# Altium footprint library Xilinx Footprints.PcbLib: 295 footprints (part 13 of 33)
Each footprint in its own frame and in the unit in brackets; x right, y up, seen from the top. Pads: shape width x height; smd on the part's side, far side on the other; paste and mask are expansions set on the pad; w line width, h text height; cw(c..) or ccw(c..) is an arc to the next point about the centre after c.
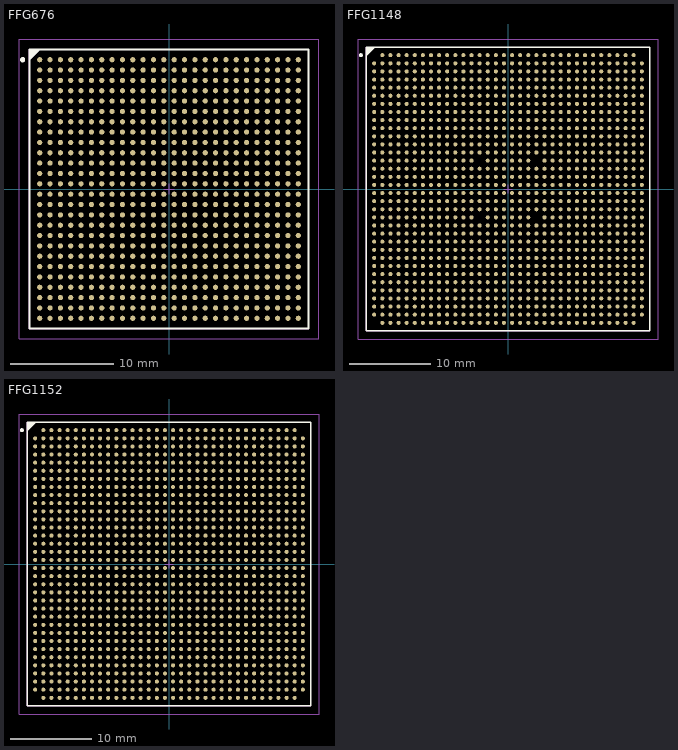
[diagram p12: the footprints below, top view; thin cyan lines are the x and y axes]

## FFG676 [mm] "676-Ball Flip Chip Fine Pitch Ball Grid Array (FFG676) - Pb-Free"
height 3
pads (676):
  round 0.5 smd: A1(-12.5,12.5) A2(-11.5,12.5) A3(-10.5,12.5) A4(-9.5,12.5) A5(-8.5,12.5) A6(-7.5,12.5) A7(-6.5,12.5) A8(-5.5,12.5) A9(-4.5,12.5) A10(-3.5,12.5) A11(-2.5,12.5) A12(-1.5,12.5) A13(-0.5,12.5) A14(0.5,12.5) A15(1.5,12.5) A16(2.5,12.5) A17(3.5,12.5) A18(4.5,12.5) A19(5.5,12.5) A20(6.5,12.5) A21(7.5,12.5) A22(8.5,12.5) A23(9.5,12.5) A24(10.5,12.5) A25(11.5,12.5) A26(12.5,12.5) AA1(-12.5,-7.5) AA2(-11.5,-7.5) AA3(-10.5,-7.5) AA4(-9.5,-7.5) AA5(-8.5,-7.5) AA6(-7.5,-7.5) AA7(-6.5,-7.5) AA8(-5.5,-7.5) AA9(-4.5,-7.5) AA10(-3.5,-7.5) AA11(-2.5,-7.5) AA12(-1.5,-7.5) AA13(-0.5,-7.5) AA14(0.5,-7.5) AA15(1.5,-7.5) AA16(2.5,-7.5) AA17(3.5,-7.5) AA18(4.5,-7.5) AA19(5.5,-7.5) AA20(6.5,-7.5) AA21(7.5,-7.5) AA22(8.5,-7.5) AA23(9.5,-7.5) AA24(10.5,-7.5) AA25(11.5,-7.5) AA26(12.5,-7.5) AB1(-12.5,-8.5) AB2(-11.5,-8.5) AB3(-10.5,-8.5) AB4(-9.5,-8.5) AB5(-8.5,-8.5) AB6(-7.5,-8.5) AB7(-6.5,-8.5) AB8(-5.5,-8.5) AB9(-4.5,-8.5) AB10(-3.5,-8.5) AB11(-2.5,-8.5) AB12(-1.5,-8.5) AB13(-0.5,-8.5) AB14(0.5,-8.5) AB15(1.5,-8.5) AB16(2.5,-8.5) AB17(3.5,-8.5) AB18(4.5,-8.5) AB19(5.5,-8.5) AB20(6.5,-8.5) AB21(7.5,-8.5) AB22(8.5,-8.5) AB23(9.5,-8.5) AB24(10.5,-8.5) AB25(11.5,-8.5) AB26(12.5,-8.5) AC1(-12.5,-9.5) AC2(-11.5,-9.5) AC3(-10.5,-9.5) AC4(-9.5,-9.5) AC5(-8.5,-9.5) AC6(-7.5,-9.5) AC7(-6.5,-9.5) AC8(-5.5,-9.5) AC9(-4.5,-9.5) AC10(-3.5,-9.5) AC11(-2.5,-9.5) AC12(-1.5,-9.5) AC13(-0.5,-9.5) AC14(0.5,-9.5) AC15(1.5,-9.5) AC16(2.5,-9.5) AC17(3.5,-9.5) AC18(4.5,-9.5) AC19(5.5,-9.5) AC20(6.5,-9.5) AC21(7.5,-9.5) AC22(8.5,-9.5) AC23(9.5,-9.5) AC24(10.5,-9.5) AC25(11.5,-9.5) AC26(12.5,-9.5) AD1(-12.5,-10.5) AD2(-11.5,-10.5) AD3(-10.5,-10.5) AD4(-9.5,-10.5) AD5(-8.5,-10.5) AD6(-7.5,-10.5) AD7(-6.5,-10.5) AD8(-5.5,-10.5) AD9(-4.5,-10.5) AD10(-3.5,-10.5) AD11(-2.5,-10.5) AD12(-1.5,-10.5) AD13(-0.5,-10.5) AD14(0.5,-10.5) AD15(1.5,-10.5) AD16(2.5,-10.5) AD17(3.5,-10.5) AD18(4.5,-10.5) AD19(5.5,-10.5) AD20(6.5,-10.5) AD21(7.5,-10.5) AD22(8.5,-10.5) AD23(9.5,-10.5) AD24(10.5,-10.5) AD25(11.5,-10.5) AD26(12.5,-10.5) AE1(-12.5,-11.5) AE2(-11.5,-11.5) AE3(-10.5,-11.5) AE4(-9.5,-11.5) AE5(-8.5,-11.5) AE6(-7.5,-11.5) AE7(-6.5,-11.5) AE8(-5.5,-11.5) AE9(-4.5,-11.5) AE10(-3.5,-11.5) AE11(-2.5,-11.5) AE12(-1.5,-11.5) AE13(-0.5,-11.5) AE14(0.5,-11.5) AE15(1.5,-11.5) AE16(2.5,-11.5) AE17(3.5,-11.5) AE18(4.5,-11.5) AE19(5.5,-11.5) AE20(6.5,-11.5) AE21(7.5,-11.5) AE22(8.5,-11.5) AE23(9.5,-11.5) AE24(10.5,-11.5) AE25(11.5,-11.5) AE26(12.5,-11.5) AF1(-12.5,-12.5) AF2(-11.5,-12.5) AF3(-10.5,-12.5) AF4(-9.5,-12.5) AF5(-8.5,-12.5) AF6(-7.5,-12.5) AF7(-6.5,-12.5) AF8(-5.5,-12.5) AF9(-4.5,-12.5) AF10(-3.5,-12.5) AF11(-2.5,-12.5) AF12(-1.5,-12.5) AF13(-0.5,-12.5) AF14(0.5,-12.5) AF15(1.5,-12.5) AF16(2.5,-12.5) AF17(3.5,-12.5) AF18(4.5,-12.5) AF19(5.5,-12.5) AF20(6.5,-12.5) AF21(7.5,-12.5) AF22(8.5,-12.5) AF23(9.5,-12.5) AF24(10.5,-12.5) AF25(11.5,-12.5) AF26(12.5,-12.5) B1(-12.5,11.5) B2(-11.5,11.5) B3(-10.5,11.5) B4(-9.5,11.5) B5(-8.5,11.5) B6(-7.5,11.5) B7(-6.5,11.5) B8(-5.5,11.5) B9(-4.5,11.5) B10(-3.5,11.5) B11(-2.5,11.5) B12(-1.5,11.5) B13(-0.5,11.5) B14(0.5,11.5) B15(1.5,11.5) B16(2.5,11.5) B17(3.5,11.5) B18(4.5,11.5) B19(5.5,11.5) B20(6.5,11.5) B21(7.5,11.5) B22(8.5,11.5) B23(9.5,11.5) B24(10.5,11.5) B25(11.5,11.5) B26(12.5,11.5) C1(-12.5,10.5) C2(-11.5,10.5) C3(-10.5,10.5) C4(-9.5,10.5) C5(-8.5,10.5) C6(-7.5,10.5) C7(-6.5,10.5) C8(-5.5,10.5) C9(-4.5,10.5) C10(-3.5,10.5) C11(-2.5,10.5) C12(-1.5,10.5) C13(-0.5,10.5) C14(0.5,10.5) C15(1.5,10.5) C16(2.5,10.5) C17(3.5,10.5) C18(4.5,10.5) C19(5.5,10.5) C20(6.5,10.5) C21(7.5,10.5) C22(8.5,10.5) C23(9.5,10.5) C24(10.5,10.5) C25(11.5,10.5) C26(12.5,10.5) D1(-12.5,9.5) D2(-11.5,9.5) D3(-10.5,9.5) D4(-9.5,9.5) D5(-8.5,9.5) D6(-7.5,9.5) D7(-6.5,9.5) D8(-5.5,9.5) D9(-4.5,9.5) D10(-3.5,9.5) D11(-2.5,9.5) D12(-1.5,9.5) D13(-0.5,9.5) D14(0.5,9.5) D15(1.5,9.5) D16(2.5,9.5) D17(3.5,9.5) D18(4.5,9.5) D19(5.5,9.5) D20(6.5,9.5) D21(7.5,9.5) D22(8.5,9.5) D23(9.5,9.5) D24(10.5,9.5) D25(11.5,9.5) D26(12.5,9.5) E1(-12.5,8.5) E2(-11.5,8.5) E3(-10.5,8.5) E4(-9.5,8.5) E5(-8.5,8.5) E6(-7.5,8.5) E7(-6.5,8.5) E8(-5.5,8.5) E9(-4.5,8.5) E10(-3.5,8.5) E11(-2.5,8.5) E12(-1.5,8.5) E13(-0.5,8.5) E14(0.5,8.5) E15(1.5,8.5) E16(2.5,8.5) E17(3.5,8.5) E18(4.5,8.5) E19(5.5,8.5) E20(6.5,8.5) E21(7.5,8.5) E22(8.5,8.5) E23(9.5,8.5) E24(10.5,8.5) E25(11.5,8.5) E26(12.5,8.5) F1(-12.5,7.5) F2(-11.5,7.5) F3(-10.5,7.5) F4(-9.5,7.5) F5(-8.5,7.5) F6(-7.5,7.5) F7(-6.5,7.5) F8(-5.5,7.5) F9(-4.5,7.5) F10(-3.5,7.5) F11(-2.5,7.5) F12(-1.5,7.5) F13(-0.5,7.5) F14(0.5,7.5) F15(1.5,7.5) F16(2.5,7.5) F17(3.5,7.5) F18(4.5,7.5) F19(5.5,7.5) F20(6.5,7.5) F21(7.5,7.5) F22(8.5,7.5) F23(9.5,7.5) F24(10.5,7.5) F25(11.5,7.5) F26(12.5,7.5) G1(-12.5,6.5) G2(-11.5,6.5) G3(-10.5,6.5) G4(-9.5,6.5) G5(-8.5,6.5) G6(-7.5,6.5) G7(-6.5,6.5) G8(-5.5,6.5) G9(-4.5,6.5) G10(-3.5,6.5) G11(-2.5,6.5) G12(-1.5,6.5) G13(-0.5,6.5) G14(0.5,6.5) G15(1.5,6.5) G16(2.5,6.5) G17(3.5,6.5) G18(4.5,6.5) G19(5.5,6.5) G20(6.5,6.5) G21(7.5,6.5) G22(8.5,6.5) G23(9.5,6.5) G24(10.5,6.5) G25(11.5,6.5) G26(12.5,6.5) H1(-12.5,5.5) H2(-11.5,5.5) H3(-10.5,5.5) H4(-9.5,5.5) H5(-8.5,5.5) H6(-7.5,5.5) H7(-6.5,5.5) H8(-5.5,5.5) H9(-4.5,5.5) H10(-3.5,5.5) H11(-2.5,5.5) H12(-1.5,5.5) H13(-0.5,5.5) H14(0.5,5.5) H15(1.5,5.5) H16(2.5,5.5) H17(3.5,5.5) H18(4.5,5.5) H19(5.5,5.5) H20(6.5,5.5) H21(7.5,5.5) H22(8.5,5.5) H23(9.5,5.5) H24(10.5,5.5) H25(11.5,5.5) H26(12.5,5.5) J1(-12.5,4.5) J2(-11.5,4.5) J3(-10.5,4.5) J4(-9.5,4.5) J5(-8.5,4.5) J6(-7.5,4.5) J7(-6.5,4.5) J8(-5.5,4.5) J9(-4.5,4.5) J10(-3.5,4.5) J11(-2.5,4.5) J12(-1.5,4.5) J13(-0.5,4.5) J14(0.5,4.5) J15(1.5,4.5) J16(2.5,4.5) J17(3.5,4.5) J18(4.5,4.5) J19(5.5,4.5) J20(6.5,4.5) J21(7.5,4.5) J22(8.5,4.5) J23(9.5,4.5) J24(10.5,4.5) J25(11.5,4.5) J26(12.5,4.5) K1(-12.5,3.5) K2(-11.5,3.5) K3(-10.5,3.5) K4(-9.5,3.5) K5(-8.5,3.5) K6(-7.5,3.5) K7(-6.5,3.5) K8(-5.5,3.5) K9(-4.5,3.5) K10(-3.5,3.5) K11(-2.5,3.5) K12(-1.5,3.5) K13(-0.5,3.5) K14(0.5,3.5) K15(1.5,3.5) K16(2.5,3.5) K17(3.5,3.5) K18(4.5,3.5) K19(5.5,3.5) K20(6.5,3.5) K21(7.5,3.5) K22(8.5,3.5) K23(9.5,3.5) K24(10.5,3.5) K25(11.5,3.5) K26(12.5,3.5) L1(-12.5,2.5) L2(-11.5,2.5) L3(-10.5,2.5) L4(-9.5,2.5) L5(-8.5,2.5) L6(-7.5,2.5) L7(-6.5,2.5) L8(-5.5,2.5) L9(-4.5,2.5) L10(-3.5,2.5) L11(-2.5,2.5) L12(-1.5,2.5) L13(-0.5,2.5) L14(0.5,2.5) L15(1.5,2.5) L16(2.5,2.5) L17(3.5,2.5) L18(4.5,2.5) L19(5.5,2.5) L20(6.5,2.5) L21(7.5,2.5) L22(8.5,2.5) L23(9.5,2.5) L24(10.5,2.5) L25(11.5,2.5) L26(12.5,2.5) M1(-12.5,1.5) M2(-11.5,1.5) M3(-10.5,1.5) M4(-9.5,1.5) M5(-8.5,1.5) M6(-7.5,1.5) M7(-6.5,1.5) M8(-5.5,1.5) M9(-4.5,1.5) M10(-3.5,1.5) M11(-2.5,1.5) M12(-1.5,1.5) M13(-0.5,1.5) M14(0.5,1.5) M15(1.5,1.5) M16(2.5,1.5) M17(3.5,1.5) M18(4.5,1.5) M19(5.5,1.5) M20(6.5,1.5) M21(7.5,1.5) M22(8.5,1.5) M23(9.5,1.5) M24(10.5,1.5) M25(11.5,1.5) M26(12.5,1.5) N1(-12.5,0.5) N2(-11.5,0.5) N3(-10.5,0.5) N4(-9.5,0.5) N5(-8.5,0.5) N6(-7.5,0.5) N7(-6.5,0.5) N8(-5.5,0.5) N9(-4.5,0.5) N10(-3.5,0.5) N11(-2.5,0.5) N12(-1.5,0.5) N13(-0.5,0.5) N14(0.5,0.5) N15(1.5,0.5) N16(2.5,0.5) N17(3.5,0.5) N18(4.5,0.5) N19(5.5,0.5) N20(6.5,0.5) N21(7.5,0.5) N22(8.5,0.5) N23(9.5,0.5) N24(10.5,0.5) N25(11.5,0.5) N26(12.5,0.5) P1(-12.5,-0.5) P2(-11.5,-0.5) P3(-10.5,-0.5) P4(-9.5,-0.5) P5(-8.5,-0.5) P6(-7.5,-0.5) P7(-6.5,-0.5) P8(-5.5,-0.5) P9(-4.5,-0.5) P10(-3.5,-0.5) P11(-2.5,-0.5) P12(-1.5,-0.5) P13(-0.5,-0.5) P14(0.5,-0.5) P15(1.5,-0.5) P16(2.5,-0.5) P17(3.5,-0.5) P18(4.5,-0.5) P19(5.5,-0.5) P20(6.5,-0.5) P21(7.5,-0.5) P22(8.5,-0.5) P23(9.5,-0.5) P24(10.5,-0.5) P25(11.5,-0.5) P26(12.5,-0.5) R1(-12.5,-1.5) R2(-11.5,-1.5) R3(-10.5,-1.5) R4(-9.5,-1.5) R5(-8.5,-1.5) R6(-7.5,-1.5) R7(-6.5,-1.5) R8(-5.5,-1.5) R9(-4.5,-1.5) R10(-3.5,-1.5) R11(-2.5,-1.5) R12(-1.5,-1.5) R13(-0.5,-1.5) R14(0.5,-1.5) R15(1.5,-1.5) R16(2.5,-1.5) R17(3.5,-1.5) R18(4.5,-1.5) R19(5.5,-1.5) R20(6.5,-1.5) R21(7.5,-1.5) R22(8.5,-1.5) R23(9.5,-1.5) R24(10.5,-1.5) R25(11.5,-1.5) R26(12.5,-1.5) T1(-12.5,-2.5) T2(-11.5,-2.5) T3(-10.5,-2.5) T4(-9.5,-2.5) T5(-8.5,-2.5) T6(-7.5,-2.5) T7(-6.5,-2.5) T8(-5.5,-2.5) T9(-4.5,-2.5) T10(-3.5,-2.5) T11(-2.5,-2.5) T12(-1.5,-2.5) T13(-0.5,-2.5) T14(0.5,-2.5) T15(1.5,-2.5) T16(2.5,-2.5) T17(3.5,-2.5) T18(4.5,-2.5) T19(5.5,-2.5) T20(6.5,-2.5) T21(7.5,-2.5) T22(8.5,-2.5) T23(9.5,-2.5) T24(10.5,-2.5) T25(11.5,-2.5) T26(12.5,-2.5) U1(-12.5,-3.5) U2(-11.5,-3.5) U3(-10.5,-3.5) U4(-9.5,-3.5) U5(-8.5,-3.5) U6(-7.5,-3.5) U7(-6.5,-3.5) U8(-5.5,-3.5) U9(-4.5,-3.5) U10(-3.5,-3.5) U11(-2.5,-3.5) U12(-1.5,-3.5) U13(-0.5,-3.5) U14(0.5,-3.5) U15(1.5,-3.5) U16(2.5,-3.5) U17(3.5,-3.5) U18(4.5,-3.5) U19(5.5,-3.5) U20(6.5,-3.5) U21(7.5,-3.5) U22(8.5,-3.5) U23(9.5,-3.5) U24(10.5,-3.5) U25(11.5,-3.5) U26(12.5,-3.5) V1(-12.5,-4.5) V2(-11.5,-4.5) V3(-10.5,-4.5) V4(-9.5,-4.5) V5(-8.5,-4.5) V6(-7.5,-4.5) V7(-6.5,-4.5) V8(-5.5,-4.5) V9(-4.5,-4.5) V10(-3.5,-4.5) V11(-2.5,-4.5) V12(-1.5,-4.5) V13(-0.5,-4.5) V14(0.5,-4.5) V15(1.5,-4.5) V16(2.5,-4.5) V17(3.5,-4.5) V18(4.5,-4.5) V19(5.5,-4.5) V20(6.5,-4.5) V21(7.5,-4.5) V22(8.5,-4.5) V23(9.5,-4.5) V24(10.5,-4.5) V25(11.5,-4.5) V26(12.5,-4.5) W1(-12.5,-5.5) W2(-11.5,-5.5) W3(-10.5,-5.5) W4(-9.5,-5.5) W5(-8.5,-5.5) W6(-7.5,-5.5) W7(-6.5,-5.5) W8(-5.5,-5.5) W9(-4.5,-5.5) W10(-3.5,-5.5) W11(-2.5,-5.5) W12(-1.5,-5.5) W13(-0.5,-5.5) W14(0.5,-5.5) W15(1.5,-5.5) W16(2.5,-5.5) W17(3.5,-5.5) W18(4.5,-5.5) W19(5.5,-5.5) W20(6.5,-5.5) W21(7.5,-5.5) W22(8.5,-5.5) W23(9.5,-5.5) W24(10.5,-5.5) W25(11.5,-5.5) W26(12.5,-5.5) Y1(-12.5,-6.5) Y2(-11.5,-6.5) Y3(-10.5,-6.5) Y4(-9.5,-6.5) Y5(-8.5,-6.5) Y6(-7.5,-6.5) Y7(-6.5,-6.5) Y8(-5.5,-6.5) Y9(-4.5,-6.5) Y10(-3.5,-6.5) Y11(-2.5,-6.5) Y12(-1.5,-6.5) Y13(-0.5,-6.5) Y14(0.5,-6.5) Y15(1.5,-6.5) Y16(2.5,-6.5) Y17(3.5,-6.5) Y18(4.5,-6.5) Y19(5.5,-6.5) Y20(6.5,-6.5) Y21(7.5,-6.5) Y22(8.5,-6.5) Y23(9.5,-6.5) Y24(10.5,-6.5) Y25(11.5,-6.5) Y26(12.5,-6.5)
Top Overlay:
  circle w0.25: c-14.15,12.5 r0.125
  region: -12.5,13.5 -13.5,12.5 -13.5,13.5
  lines w0.2: -13.5,12.5 -12.5,13.5 ; -13.5,-13.5 13.5,-13.5 13.5,13.5 -13.5,13.5 -13.5,-13.5
Mechanical 13:
  lines w0.1: -13.5,-13.5 13.5,-13.5 13.5,13.5 -13.5,13.5 -13.5,-13.5
Mechanical 15:
  lines w0.1: -0.5,0 0.5,0 ; 0,-0.5 0,0.5 ; -14.5,-14.5 14.5,-14.5 14.5,14.5 -14.5,14.5 -14.5,-14.5
3D body: height 3, standoff 0, extent -13.5,-13.5 13.5,13.5

## FFG1148 [mm] "1148-Ball Flip Chip Fine Pitch Ball Grid Array (FFG1148) - Pb-Free"
height 3.4
pads (1148):
  round 0.5 smd: A2(-15.5,16.5) A3(-14.5,16.5) A4(-13.5,16.5) A5(-12.5,16.5) A6(-11.5,16.5) A7(-10.5,16.5) A8(-9.5,16.5) A9(-8.5,16.5) A10(-7.5,16.5) A11(-6.5,16.5) A12(-5.5,16.5) A13(-4.5,16.5) A14(-3.5,16.5) A15(-2.5,16.5) A16(-1.5,16.5) A17(-0.5,16.5) A18(0.5,16.5) A19(1.5,16.5) A20(2.5,16.5) A21(3.5,16.5) A22(4.5,16.5) A23(5.5,16.5) A24(6.5,16.5) A25(7.5,16.5) A26(8.5,16.5) A27(9.5,16.5) A28(10.5,16.5) A29(11.5,16.5) A30(12.5,16.5) A31(13.5,16.5) A32(14.5,16.5) A33(15.5,16.5) AA1(-16.5,-3.5) AA2(-15.5,-3.5) AA3(-14.5,-3.5) AA4(-13.5,-3.5) AA5(-12.5,-3.5) AA6(-11.5,-3.5) AA7(-10.5,-3.5) AA8(-9.5,-3.5) AA9(-8.5,-3.5) AA10(-7.5,-3.5) AA11(-6.5,-3.5) AA12(-5.5,-3.5) AA13(-4.5,-3.5) AA15(-2.5,-3.5) AA16(-1.5,-3.5) AA17(-0.5,-3.5) AA18(0.5,-3.5) AA19(1.5,-3.5) AA20(2.5,-3.5) AA22(4.5,-3.5) AA23(5.5,-3.5) AA24(6.5,-3.5) AA25(7.5,-3.5) AA26(8.5,-3.5) AA27(9.5,-3.5) AA28(10.5,-3.5) AA29(11.5,-3.5) AA30(12.5,-3.5) AA31(13.5,-3.5) AA32(14.5,-3.5) AA33(15.5,-3.5) AA34(16.5,-3.5) AB1(-16.5,-4.5) AB2(-15.5,-4.5) AB3(-14.5,-4.5) AB4(-13.5,-4.5) AB5(-12.5,-4.5) AB6(-11.5,-4.5) AB7(-10.5,-4.5) AB8(-9.5,-4.5) AB9(-8.5,-4.5) AB10(-7.5,-4.5) AB11(-6.5,-4.5) AB12(-5.5,-4.5) AB13(-4.5,-4.5) AB14(-3.5,-4.5) AB15(-2.5,-4.5) AB16(-1.5,-4.5) AB17(-0.5,-4.5) AB18(0.5,-4.5) AB19(1.5,-4.5) AB20(2.5,-4.5) AB21(3.5,-4.5) AB22(4.5,-4.5) AB23(5.5,-4.5) AB24(6.5,-4.5) AB25(7.5,-4.5) AB26(8.5,-4.5) AB27(9.5,-4.5) AB28(10.5,-4.5) AB29(11.5,-4.5) AB30(12.5,-4.5) AB31(13.5,-4.5) AB32(14.5,-4.5) AB33(15.5,-4.5) AB34(16.5,-4.5) AC1(-16.5,-5.5) AC2(-15.5,-5.5) AC3(-14.5,-5.5) AC4(-13.5,-5.5) AC5(-12.5,-5.5) AC6(-11.5,-5.5) AC7(-10.5,-5.5) AC8(-9.5,-5.5) AC9(-8.5,-5.5) AC10(-7.5,-5.5) AC11(-6.5,-5.5) AC12(-5.5,-5.5) AC13(-4.5,-5.5) AC14(-3.5,-5.5) AC15(-2.5,-5.5) AC16(-1.5,-5.5) AC17(-0.5,-5.5) AC18(0.5,-5.5) AC19(1.5,-5.5) AC20(2.5,-5.5) AC21(3.5,-5.5) AC22(4.5,-5.5) AC23(5.5,-5.5) AC24(6.5,-5.5) AC25(7.5,-5.5) AC26(8.5,-5.5) AC27(9.5,-5.5) AC28(10.5,-5.5) AC29(11.5,-5.5) AC30(12.5,-5.5) AC31(13.5,-5.5) AC32(14.5,-5.5) AC33(15.5,-5.5) AC34(16.5,-5.5) AD1(-16.5,-6.5) AD2(-15.5,-6.5) AD3(-14.5,-6.5) AD4(-13.5,-6.5) AD5(-12.5,-6.5) AD6(-11.5,-6.5) AD7(-10.5,-6.5) AD8(-9.5,-6.5) AD9(-8.5,-6.5) AD10(-7.5,-6.5) AD11(-6.5,-6.5) AD12(-5.5,-6.5) AD13(-4.5,-6.5) AD14(-3.5,-6.5) AD15(-2.5,-6.5) AD16(-1.5,-6.5) AD17(-0.5,-6.5) AD18(0.5,-6.5) AD19(1.5,-6.5) AD20(2.5,-6.5) AD21(3.5,-6.5) AD22(4.5,-6.5) AD23(5.5,-6.5) AD24(6.5,-6.5) AD25(7.5,-6.5) AD26(8.5,-6.5) AD27(9.5,-6.5) AD28(10.5,-6.5) AD29(11.5,-6.5) AD30(12.5,-6.5) AD31(13.5,-6.5) AD32(14.5,-6.5) AD33(15.5,-6.5) AD34(16.5,-6.5) AE1(-16.5,-7.5) AE2(-15.5,-7.5) AE3(-14.5,-7.5) AE4(-13.5,-7.5) AE5(-12.5,-7.5) AE6(-11.5,-7.5) AE7(-10.5,-7.5) AE8(-9.5,-7.5) AE9(-8.5,-7.5) AE10(-7.5,-7.5) AE11(-6.5,-7.5) AE12(-5.5,-7.5) AE13(-4.5,-7.5) AE14(-3.5,-7.5) AE15(-2.5,-7.5) AE16(-1.5,-7.5) AE17(-0.5,-7.5) AE18(0.5,-7.5) AE19(1.5,-7.5) AE20(2.5,-7.5) AE21(3.5,-7.5) AE22(4.5,-7.5) AE23(5.5,-7.5) AE24(6.5,-7.5) AE25(7.5,-7.5) AE26(8.5,-7.5) AE27(9.5,-7.5) AE28(10.5,-7.5) AE29(11.5,-7.5) AE30(12.5,-7.5) AE31(13.5,-7.5) AE32(14.5,-7.5) AE33(15.5,-7.5) AE34(16.5,-7.5) AF1(-16.5,-8.5) AF2(-15.5,-8.5) AF3(-14.5,-8.5) AF4(-13.5,-8.5) AF5(-12.5,-8.5) AF6(-11.5,-8.5) AF7(-10.5,-8.5) AF8(-9.5,-8.5) AF9(-8.5,-8.5) AF10(-7.5,-8.5) AF11(-6.5,-8.5) AF12(-5.5,-8.5) AF13(-4.5,-8.5) AF14(-3.5,-8.5) AF15(-2.5,-8.5) AF16(-1.5,-8.5) AF17(-0.5,-8.5) AF18(0.5,-8.5) AF19(1.5,-8.5) AF20(2.5,-8.5) AF21(3.5,-8.5) AF22(4.5,-8.5) AF23(5.5,-8.5) AF24(6.5,-8.5) AF25(7.5,-8.5) AF26(8.5,-8.5) AF27(9.5,-8.5) AF28(10.5,-8.5) AF29(11.5,-8.5) AF30(12.5,-8.5) AF31(13.5,-8.5) AF32(14.5,-8.5) AF33(15.5,-8.5) AF34(16.5,-8.5) AG1(-16.5,-9.5) AG2(-15.5,-9.5) AG3(-14.5,-9.5) AG4(-13.5,-9.5) AG5(-12.5,-9.5) AG6(-11.5,-9.5) AG7(-10.5,-9.5) AG8(-9.5,-9.5) AG9(-8.5,-9.5) AG10(-7.5,-9.5) AG11(-6.5,-9.5) AG12(-5.5,-9.5) AG13(-4.5,-9.5) AG14(-3.5,-9.5) AG15(-2.5,-9.5) AG16(-1.5,-9.5) AG17(-0.5,-9.5) AG18(0.5,-9.5) AG19(1.5,-9.5) AG20(2.5,-9.5) AG21(3.5,-9.5) AG22(4.5,-9.5) AG23(5.5,-9.5) AG24(6.5,-9.5) AG25(7.5,-9.5) AG26(8.5,-9.5) AG27(9.5,-9.5) AG28(10.5,-9.5) AG29(11.5,-9.5) AG30(12.5,-9.5) AG31(13.5,-9.5) AG32(14.5,-9.5) AG33(15.5,-9.5) AG34(16.5,-9.5) AH1(-16.5,-10.5) AH2(-15.5,-10.5) AH3(-14.5,-10.5) AH4(-13.5,-10.5) AH5(-12.5,-10.5) AH6(-11.5,-10.5) AH7(-10.5,-10.5) AH8(-9.5,-10.5) AH9(-8.5,-10.5) AH10(-7.5,-10.5) AH11(-6.5,-10.5) AH12(-5.5,-10.5) AH13(-4.5,-10.5) AH14(-3.5,-10.5) AH15(-2.5,-10.5) AH16(-1.5,-10.5) AH17(-0.5,-10.5) AH18(0.5,-10.5) AH19(1.5,-10.5) AH20(2.5,-10.5) AH21(3.5,-10.5) AH22(4.5,-10.5) AH23(5.5,-10.5) AH24(6.5,-10.5) AH25(7.5,-10.5) AH26(8.5,-10.5) AH27(9.5,-10.5) AH28(10.5,-10.5) AH29(11.5,-10.5) AH30(12.5,-10.5) AH31(13.5,-10.5) AH32(14.5,-10.5) AH33(15.5,-10.5) AH34(16.5,-10.5) AJ1(-16.5,-11.5) AJ2(-15.5,-11.5) AJ3(-14.5,-11.5) AJ4(-13.5,-11.5) AJ5(-12.5,-11.5) AJ6(-11.5,-11.5) AJ7(-10.5,-11.5) AJ8(-9.5,-11.5) AJ9(-8.5,-11.5) AJ10(-7.5,-11.5) AJ11(-6.5,-11.5) AJ12(-5.5,-11.5) AJ13(-4.5,-11.5) AJ14(-3.5,-11.5) AJ15(-2.5,-11.5) AJ16(-1.5,-11.5) AJ17(-0.5,-11.5) AJ18(0.5,-11.5) AJ19(1.5,-11.5) AJ20(2.5,-11.5) AJ21(3.5,-11.5) AJ22(4.5,-11.5) AJ23(5.5,-11.5) AJ24(6.5,-11.5) AJ25(7.5,-11.5) AJ26(8.5,-11.5) AJ27(9.5,-11.5) AJ28(10.5,-11.5) AJ29(11.5,-11.5) AJ30(12.5,-11.5) AJ31(13.5,-11.5) AJ32(14.5,-11.5) AJ33(15.5,-11.5) AJ34(16.5,-11.5) AK1(-16.5,-12.5) AK2(-15.5,-12.5) AK3(-14.5,-12.5) AK4(-13.5,-12.5) AK5(-12.5,-12.5) AK6(-11.5,-12.5) AK7(-10.5,-12.5) AK8(-9.5,-12.5) AK9(-8.5,-12.5) AK10(-7.5,-12.5) AK11(-6.5,-12.5) AK12(-5.5,-12.5) AK13(-4.5,-12.5) AK14(-3.5,-12.5) AK15(-2.5,-12.5) AK16(-1.5,-12.5) AK17(-0.5,-12.5) AK18(0.5,-12.5) AK19(1.5,-12.5) AK20(2.5,-12.5) AK21(3.5,-12.5) AK22(4.5,-12.5) AK23(5.5,-12.5) AK24(6.5,-12.5) AK25(7.5,-12.5) AK26(8.5,-12.5) AK27(9.5,-12.5) AK28(10.5,-12.5) AK29(11.5,-12.5) AK30(12.5,-12.5) AK31(13.5,-12.5) AK32(14.5,-12.5) AK33(15.5,-12.5) AK34(16.5,-12.5) AL1(-16.5,-13.5) AL2(-15.5,-13.5) AL3(-14.5,-13.5) AL4(-13.5,-13.5) AL5(-12.5,-13.5) AL6(-11.5,-13.5) AL7(-10.5,-13.5) AL8(-9.5,-13.5) AL9(-8.5,-13.5) AL10(-7.5,-13.5) AL11(-6.5,-13.5) AL12(-5.5,-13.5) AL13(-4.5,-13.5) AL14(-3.5,-13.5) AL15(-2.5,-13.5) AL16(-1.5,-13.5) AL17(-0.5,-13.5) AL18(0.5,-13.5) AL19(1.5,-13.5) AL20(2.5,-13.5) AL21(3.5,-13.5) AL22(4.5,-13.5) AL23(5.5,-13.5) AL24(6.5,-13.5) AL25(7.5,-13.5) AL26(8.5,-13.5) AL27(9.5,-13.5) AL28(10.5,-13.5) AL29(11.5,-13.5) AL30(12.5,-13.5) AL31(13.5,-13.5) AL32(14.5,-13.5) AL33(15.5,-13.5) AL34(16.5,-13.5) AM1(-16.5,-14.5) AM2(-15.5,-14.5) AM3(-14.5,-14.5) AM4(-13.5,-14.5) AM5(-12.5,-14.5) AM6(-11.5,-14.5) AM7(-10.5,-14.5) AM8(-9.5,-14.5) AM9(-8.5,-14.5) AM10(-7.5,-14.5) AM11(-6.5,-14.5) AM12(-5.5,-14.5) AM13(-4.5,-14.5) AM14(-3.5,-14.5) AM15(-2.5,-14.5) AM16(-1.5,-14.5) AM17(-0.5,-14.5) AM18(0.5,-14.5) AM19(1.5,-14.5) AM20(2.5,-14.5) AM21(3.5,-14.5) AM22(4.5,-14.5) AM23(5.5,-14.5) AM24(6.5,-14.5) AM25(7.5,-14.5) AM26(8.5,-14.5) AM27(9.5,-14.5) AM28(10.5,-14.5) AM29(11.5,-14.5) AM30(12.5,-14.5) AM31(13.5,-14.5) AM32(14.5,-14.5) AM33(15.5,-14.5) AM34(16.5,-14.5) AN1(-16.5,-15.5) AN2(-15.5,-15.5) AN3(-14.5,-15.5) AN4(-13.5,-15.5) AN5(-12.5,-15.5) AN6(-11.5,-15.5) AN7(-10.5,-15.5) AN8(-9.5,-15.5) AN9(-8.5,-15.5) AN10(-7.5,-15.5) AN11(-6.5,-15.5) AN12(-5.5,-15.5) AN13(-4.5,-15.5) AN14(-3.5,-15.5) AN15(-2.5,-15.5) AN16(-1.5,-15.5) AN17(-0.5,-15.5) AN18(0.5,-15.5) AN19(1.5,-15.5) AN20(2.5,-15.5) AN21(3.5,-15.5) AN22(4.5,-15.5) AN23(5.5,-15.5) AN24(6.5,-15.5) AN25(7.5,-15.5) AN26(8.5,-15.5) AN27(9.5,-15.5) AN28(10.5,-15.5) AN29(11.5,-15.5) AN30(12.5,-15.5) AN31(13.5,-15.5) AN32(14.5,-15.5) AN33(15.5,-15.5) AN34(16.5,-15.5) AP2(-15.5,-16.5) AP3(-14.5,-16.5) AP4(-13.5,-16.5) AP5(-12.5,-16.5) AP6(-11.5,-16.5) AP7(-10.5,-16.5) AP8(-9.5,-16.5) AP9(-8.5,-16.5) AP10(-7.5,-16.5) AP11(-6.5,-16.5) AP12(-5.5,-16.5) AP13(-4.5,-16.5) AP14(-3.5,-16.5) AP15(-2.5,-16.5) AP16(-1.5,-16.5) AP17(-0.5,-16.5) AP18(0.5,-16.5) AP19(1.5,-16.5) AP20(2.5,-16.5) AP21(3.5,-16.5) AP22(4.5,-16.5) AP23(5.5,-16.5) AP24(6.5,-16.5) AP25(7.5,-16.5) AP26(8.5,-16.5) AP27(9.5,-16.5) AP28(10.5,-16.5) AP29(11.5,-16.5) AP30(12.5,-16.5) AP31(13.5,-16.5) AP32(14.5,-16.5) AP33(15.5,-16.5) B1(-16.5,15.5) B2(-15.5,15.5) B3(-14.5,15.5) B4(-13.5,15.5) B5(-12.5,15.5) B6(-11.5,15.5) B7(-10.5,15.5) B8(-9.5,15.5) B9(-8.5,15.5) B10(-7.5,15.5) B11(-6.5,15.5) B12(-5.5,15.5) B13(-4.5,15.5) B14(-3.5,15.5) B15(-2.5,15.5) B16(-1.5,15.5) B17(-0.5,15.5) B18(0.5,15.5) B19(1.5,15.5) B20(2.5,15.5) B21(3.5,15.5) B22(4.5,15.5) B23(5.5,15.5) B24(6.5,15.5) B25(7.5,15.5) B26(8.5,15.5) B27(9.5,15.5) B28(10.5,15.5) B29(11.5,15.5) B30(12.5,15.5) B31(13.5,15.5) B32(14.5,15.5) B33(15.5,15.5) B34(16.5,15.5) C1(-16.5,14.5) C2(-15.5,14.5) C3(-14.5,14.5) C4(-13.5,14.5) C5(-12.5,14.5) C6(-11.5,14.5) C7(-10.5,14.5) C8(-9.5,14.5) C9(-8.5,14.5) C10(-7.5,14.5) C11(-6.5,14.5) C12(-5.5,14.5) C13(-4.5,14.5) C14(-3.5,14.5) C15(-2.5,14.5) C16(-1.5,14.5) C17(-0.5,14.5) C18(0.5,14.5) C19(1.5,14.5) C20(2.5,14.5) C21(3.5,14.5) C22(4.5,14.5) C23(5.5,14.5) C24(6.5,14.5) C25(7.5,14.5) C26(8.5,14.5) C27(9.5,14.5) C28(10.5,14.5) C29(11.5,14.5) C30(12.5,14.5) C31(13.5,14.5) C32(14.5,14.5) C33(15.5,14.5) C34(16.5,14.5) D1(-16.5,13.5) D2(-15.5,13.5) D3(-14.5,13.5) D4(-13.5,13.5) D5(-12.5,13.5) D6(-11.5,13.5) D7(-10.5,13.5) D8(-9.5,13.5) D9(-8.5,13.5) D10(-7.5,13.5) D11(-6.5,13.5) D12(-5.5,13.5) D13(-4.5,13.5) D14(-3.5,13.5) D15(-2.5,13.5) D16(-1.5,13.5) D17(-0.5,13.5) D18(0.5,13.5) D19(1.5,13.5) D20(2.5,13.5) D21(3.5,13.5) D22(4.5,13.5) D23(5.5,13.5) D24(6.5,13.5) D25(7.5,13.5) D26(8.5,13.5) D27(9.5,13.5) D28(10.5,13.5) D29(11.5,13.5) D30(12.5,13.5) D31(13.5,13.5) D32(14.5,13.5) D33(15.5,13.5) D34(16.5,13.5) E1(-16.5,12.5) E2(-15.5,12.5) E3(-14.5,12.5) E4(-13.5,12.5) E5(-12.5,12.5) E6(-11.5,12.5) E7(-10.5,12.5) E8(-9.5,12.5) E9(-8.5,12.5) E10(-7.5,12.5) E11(-6.5,12.5) E12(-5.5,12.5) E13(-4.5,12.5) E14(-3.5,12.5) E15(-2.5,12.5) E16(-1.5,12.5) E17(-0.5,12.5) E18(0.5,12.5) E19(1.5,12.5) E20(2.5,12.5) E21(3.5,12.5) E22(4.5,12.5) E23(5.5,12.5) E24(6.5,12.5) E25(7.5,12.5) E26(8.5,12.5) E27(9.5,12.5) E28(10.5,12.5) E29(11.5,12.5) E30(12.5,12.5) E31(13.5,12.5) E32(14.5,12.5) E33(15.5,12.5) E34(16.5,12.5) F1(-16.5,11.5) F2(-15.5,11.5) F3(-14.5,11.5) F4(-13.5,11.5) F5(-12.5,11.5) F6(-11.5,11.5) F7(-10.5,11.5) F8(-9.5,11.5) F9(-8.5,11.5) F10(-7.5,11.5) F11(-6.5,11.5) F12(-5.5,11.5) F13(-4.5,11.5) F14(-3.5,11.5) F15(-2.5,11.5) F16(-1.5,11.5) F17(-0.5,11.5) F18(0.5,11.5) F19(1.5,11.5) F20(2.5,11.5) F21(3.5,11.5) F22(4.5,11.5) F23(5.5,11.5) F24(6.5,11.5) F25(7.5,11.5) F26(8.5,11.5) F27(9.5,11.5) F28(10.5,11.5) F29(11.5,11.5) F30(12.5,11.5) F31(13.5,11.5) F32(14.5,11.5) F33(15.5,11.5) F34(16.5,11.5) G1(-16.5,10.5) G2(-15.5,10.5) G3(-14.5,10.5) G4(-13.5,10.5) G5(-12.5,10.5) G6(-11.5,10.5) G7(-10.5,10.5) G8(-9.5,10.5) G9(-8.5,10.5) G10(-7.5,10.5) G11(-6.5,10.5) G12(-5.5,10.5) G13(-4.5,10.5) G14(-3.5,10.5) G15(-2.5,10.5) G16(-1.5,10.5) G17(-0.5,10.5) G18(0.5,10.5) G19(1.5,10.5) G20(2.5,10.5) G21(3.5,10.5) G22(4.5,10.5) G23(5.5,10.5) G24(6.5,10.5) G25(7.5,10.5) G26(8.5,10.5) G27(9.5,10.5) G28(10.5,10.5) G29(11.5,10.5) G30(12.5,10.5) G31(13.5,10.5) G32(14.5,10.5) G33(15.5,10.5) G34(16.5,10.5) H1(-16.5,9.5) H2(-15.5,9.5) H3(-14.5,9.5) H4(-13.5,9.5) H5(-12.5,9.5) H6(-11.5,9.5) H7(-10.5,9.5) H8(-9.5,9.5) H9(-8.5,9.5) H10(-7.5,9.5) H11(-6.5,9.5) H12(-5.5,9.5) H13(-4.5,9.5) H14(-3.5,9.5) H15(-2.5,9.5) H16(-1.5,9.5) H17(-0.5,9.5) H18(0.5,9.5) H19(1.5,9.5) H20(2.5,9.5) H21(3.5,9.5) H22(4.5,9.5) H23(5.5,9.5) H24(6.5,9.5) H25(7.5,9.5) H26(8.5,9.5) H27(9.5,9.5) H28(10.5,9.5) H29(11.5,9.5) H30(12.5,9.5) H31(13.5,9.5) H32(14.5,9.5) H33(15.5,9.5) H34(16.5,9.5) J1(-16.5,8.5) J2(-15.5,8.5) J3(-14.5,8.5) J4(-13.5,8.5) J5(-12.5,8.5) J6(-11.5,8.5) J7(-10.5,8.5) J8(-9.5,8.5) J9(-8.5,8.5) J10(-7.5,8.5) J11(-6.5,8.5) J12(-5.5,8.5) J13(-4.5,8.5) J14(-3.5,8.5) J15(-2.5,8.5) J16(-1.5,8.5) J17(-0.5,8.5) J18(0.5,8.5) J19(1.5,8.5) J20(2.5,8.5) J21(3.5,8.5) J22(4.5,8.5) J23(5.5,8.5) J24(6.5,8.5) J25(7.5,8.5) J26(8.5,8.5) J27(9.5,8.5) J28(10.5,8.5) J29(11.5,8.5) J30(12.5,8.5) J31(13.5,8.5) J32(14.5,8.5) J33(15.5,8.5) J34(16.5,8.5) K1(-16.5,7.5) K2(-15.5,7.5) K3(-14.5,7.5) K4(-13.5,7.5) K5(-12.5,7.5) K6(-11.5,7.5) K7(-10.5,7.5) K8(-9.5,7.5) K9(-8.5,7.5) K10(-7.5,7.5) K11(-6.5,7.5) K12(-5.5,7.5) K13(-4.5,7.5) K14(-3.5,7.5) K15(-2.5,7.5) K16(-1.5,7.5) K17(-0.5,7.5) K18(0.5,7.5) K19(1.5,7.5) K20(2.5,7.5) K21(3.5,7.5) K22(4.5,7.5) K23(5.5,7.5) K24(6.5,7.5) K25(7.5,7.5) K26(8.5,7.5) K27(9.5,7.5) K28(10.5,7.5) K29(11.5,7.5) K30(12.5,7.5) K31(13.5,7.5) K32(14.5,7.5) K33(15.5,7.5) K34(16.5,7.5) L1(-16.5,6.5) L2(-15.5,6.5) L3(-14.5,6.5) L4(-13.5,6.5) L5(-12.5,6.5) L6(-11.5,6.5) L7(-10.5,6.5) L8(-9.5,6.5) L9(-8.5,6.5) L10(-7.5,6.5) L11(-6.5,6.5) L12(-5.5,6.5) L13(-4.5,6.5) L14(-3.5,6.5) L15(-2.5,6.5) L16(-1.5,6.5) L17(-0.5,6.5) L18(0.5,6.5) L19(1.5,6.5) L20(2.5,6.5) L21(3.5,6.5) L22(4.5,6.5) L23(5.5,6.5) L24(6.5,6.5) L25(7.5,6.5) L26(8.5,6.5) L27(9.5,6.5) L28(10.5,6.5) L29(11.5,6.5) L30(12.5,6.5) L31(13.5,6.5) L32(14.5,6.5) L33(15.5,6.5) L34(16.5,6.5) M1(-16.5,5.5) M2(-15.5,5.5) M3(-14.5,5.5) M4(-13.5,5.5) M5(-12.5,5.5) M6(-11.5,5.5) M7(-10.5,5.5) M8(-9.5,5.5) M9(-8.5,5.5) M10(-7.5,5.5) M11(-6.5,5.5) M12(-5.5,5.5) M13(-4.5,5.5) M14(-3.5,5.5) M15(-2.5,5.5) M16(-1.5,5.5) M17(-0.5,5.5) M18(0.5,5.5) M19(1.5,5.5) M20(2.5,5.5) M21(3.5,5.5) M22(4.5,5.5) M23(5.5,5.5) M24(6.5,5.5) M25(7.5,5.5) M26(8.5,5.5) M27(9.5,5.5) M28(10.5,5.5) M29(11.5,5.5) M30(12.5,5.5) M31(13.5,5.5) M32(14.5,5.5) M33(15.5,5.5) M34(16.5,5.5) N1(-16.5,4.5) N2(-15.5,4.5) N3(-14.5,4.5) N4(-13.5,4.5) N5(-12.5,4.5) N6(-11.5,4.5) N7(-10.5,4.5) N8(-9.5,4.5) N9(-8.5,4.5) N10(-7.5,4.5) N11(-6.5,4.5) N12(-5.5,4.5) N13(-4.5,4.5) N14(-3.5,4.5) N15(-2.5,4.5) N16(-1.5,4.5) N17(-0.5,4.5) N18(0.5,4.5) N19(1.5,4.5) N20(2.5,4.5) N21(3.5,4.5) N22(4.5,4.5) N23(5.5,4.5) N24(6.5,4.5) N25(7.5,4.5) N26(8.5,4.5) N27(9.5,4.5) N28(10.5,4.5) N29(11.5,4.5) N30(12.5,4.5) N31(13.5,4.5) N32(14.5,4.5) N33(15.5,4.5) N34(16.5,4.5) P1(-16.5,3.5) P2(-15.5,3.5) P3(-14.5,3.5) P4(-13.5,3.5) P5(-12.5,3.5) P6(-11.5,3.5) P7(-10.5,3.5) P8(-9.5,3.5) P9(-8.5,3.5) P10(-7.5,3.5) P11(-6.5,3.5) P12(-5.5,3.5) P13(-4.5,3.5) P15(-2.5,3.5) P16(-1.5,3.5) P17(-0.5,3.5) P18(0.5,3.5) P19(1.5,3.5) P20(2.5,3.5) P22(4.5,3.5) P23(5.5,3.5) P24(6.5,3.5) P25(7.5,3.5) P26(8.5,3.5) P27(9.5,3.5) P28(10.5,3.5) P29(11.5,3.5) P30(12.5,3.5) P31(13.5,3.5) P32(14.5,3.5) P33(15.5,3.5) P34(16.5,3.5) R1(-16.5,2.5) R2(-15.5,2.5) R3(-14.5,2.5) R4(-13.5,2.5) R5(-12.5,2.5) R6(-11.5,2.5) R7(-10.5,2.5) R8(-9.5,2.5) R9(-8.5,2.5) R10(-7.5,2.5) R11(-6.5,2.5) R12(-5.5,2.5) R13(-4.5,2.5) R14(-3.5,2.5) R15(-2.5,2.5) R16(-1.5,2.5) R17(-0.5,2.5) R18(0.5,2.5) R19(1.5,2.5) R20(2.5,2.5) R21(3.5,2.5) R22(4.5,2.5) R23(5.5,2.5) R24(6.5,2.5) R25(7.5,2.5) R26(8.5,2.5) R27(9.5,2.5) R28(10.5,2.5) R29(11.5,2.5) R30(12.5,2.5) R31(13.5,2.5) R32(14.5,2.5) R33(15.5,2.5) R34(16.5,2.5) T1(-16.5,1.5) T2(-15.5,1.5) T3(-14.5,1.5) T4(-13.5,1.5) T5(-12.5,1.5) T6(-11.5,1.5) T7(-10.5,1.5) T8(-9.5,1.5) T9(-8.5,1.5) T10(-7.5,1.5) T11(-6.5,1.5) T12(-5.5,1.5) T13(-4.5,1.5) T14(-3.5,1.5) T15(-2.5,1.5) T16(-1.5,1.5) T17(-0.5,1.5) T18(0.5,1.5) T19(1.5,1.5) T20(2.5,1.5) T21(3.5,1.5) T22(4.5,1.5) T23(5.5,1.5) T24(6.5,1.5) T25(7.5,1.5) T26(8.5,1.5) T27(9.5,1.5) T28(10.5,1.5) T29(11.5,1.5) T30(12.5,1.5) T31(13.5,1.5) T32(14.5,1.5) T33(15.5,1.5) T34(16.5,1.5) U1(-16.5,0.5) U2(-15.5,0.5) U3(-14.5,0.5) U4(-13.5,0.5) U5(-12.5,0.5) U6(-11.5,0.5) U7(-10.5,0.5) U8(-9.5,0.5) U9(-8.5,0.5) U10(-7.5,0.5) U11(-6.5,0.5) U12(-5.5,0.5) U13(-4.5,0.5) U14(-3.5,0.5) U15(-2.5,0.5) U16(-1.5,0.5) U17(-0.5,0.5) U18(0.5,0.5) U19(1.5,0.5) U20(2.5,0.5) U21(3.5,0.5) U22(4.5,0.5) U23(5.5,0.5) U24(6.5,0.5) U25(7.5,0.5) U26(8.5,0.5) U27(9.5,0.5) U28(10.5,0.5) U29(11.5,0.5) U30(12.5,0.5) U31(13.5,0.5) U32(14.5,0.5) U33(15.5,0.5) U34(16.5,0.5) V1(-16.5,-0.5) V2(-15.5,-0.5) V3(-14.5,-0.5) V4(-13.5,-0.5) V5(-12.5,-0.5) V6(-11.5,-0.5) V7(-10.5,-0.5) V8(-9.5,-0.5) V9(-8.5,-0.5) V10(-7.5,-0.5) V11(-6.5,-0.5) V12(-5.5,-0.5) V13(-4.5,-0.5) V14(-3.5,-0.5) V15(-2.5,-0.5) V16(-1.5,-0.5) V17(-0.5,-0.5) V18(0.5,-0.5) V19(1.5,-0.5) V20(2.5,-0.5) V21(3.5,-0.5) V22(4.5,-0.5) V23(5.5,-0.5) V24(6.5,-0.5) V25(7.5,-0.5) V26(8.5,-0.5) V27(9.5,-0.5) V28(10.5,-0.5) V29(11.5,-0.5) V30(12.5,-0.5) V31(13.5,-0.5) V32(14.5,-0.5) V33(15.5,-0.5) V34(16.5,-0.5) W1(-16.5,-1.5) W2(-15.5,-1.5) W3(-14.5,-1.5) W4(-13.5,-1.5) W5(-12.5,-1.5) W6(-11.5,-1.5) W7(-10.5,-1.5) W8(-9.5,-1.5) W9(-8.5,-1.5) W10(-7.5,-1.5) W11(-6.5,-1.5) W12(-5.5,-1.5) W13(-4.5,-1.5) W14(-3.5,-1.5) W15(-2.5,-1.5) W16(-1.5,-1.5) W17(-0.5,-1.5) W18(0.5,-1.5) W19(1.5,-1.5) W20(2.5,-1.5) W21(3.5,-1.5) W22(4.5,-1.5) W23(5.5,-1.5) W24(6.5,-1.5) W25(7.5,-1.5) W26(8.5,-1.5) W27(9.5,-1.5) W28(10.5,-1.5) W29(11.5,-1.5) W30(12.5,-1.5) W31(13.5,-1.5) W32(14.5,-1.5) W33(15.5,-1.5) W34(16.5,-1.5) Y1(-16.5,-2.5) Y2(-15.5,-2.5) Y3(-14.5,-2.5) Y4(-13.5,-2.5) Y5(-12.5,-2.5) Y6(-11.5,-2.5) Y7(-10.5,-2.5) Y8(-9.5,-2.5) Y9(-8.5,-2.5) Y10(-7.5,-2.5) Y11(-6.5,-2.5) Y12(-5.5,-2.5) Y13(-4.5,-2.5) Y14(-3.5,-2.5) Y15(-2.5,-2.5) Y16(-1.5,-2.5) Y17(-0.5,-2.5) Y18(0.5,-2.5) Y19(1.5,-2.5) Y20(2.5,-2.5) Y21(3.5,-2.5) Y22(4.5,-2.5) Y23(5.5,-2.5) Y24(6.5,-2.5) Y25(7.5,-2.5) Y26(8.5,-2.5) Y27(9.5,-2.5) Y28(10.5,-2.5) Y29(11.5,-2.5) Y30(12.5,-2.5) Y31(13.5,-2.5) Y32(14.5,-2.5) Y33(15.5,-2.5) Y34(16.5,-2.5)
Top Overlay:
  circle w0.25: c-18.15,16.5 r0.125
  region: -16.5,17.5 -17.5,16.5 -17.5,17.5
  lines w0.2: -17.5,16.5 -16.5,17.5 ; -17.5,-17.5 -17.5,17.5 17.5,17.5 17.5,-17.5 -17.5,-17.5
Mechanical 13:
  lines w0.1: -17.5,-17.5 -17.5,17.5 17.5,17.5 17.5,-17.5 -17.5,-17.5
Mechanical 15:
  lines w0.1: -0.5,0 0.5,0 ; 0,-0.5 0,0.5 ; -18.5,-18.5 -18.5,18.5 18.5,18.5 18.5,-18.5 -18.5,-18.5
3D body: height 3.4, standoff 0, extent -17.5,-17.5 17.5,17.5

## FFG1152 [mm] "1152-Ball Flip Chip Fine Pitch Ball Grid Array (FFG1152) - Pb-Free"
height 3.4
pads (1152):
  round 0.5 smd: A2(-15.5,16.5) A3(-14.5,16.5) A4(-13.5,16.5) A5(-12.5,16.5) A6(-11.5,16.5) A7(-10.5,16.5) A8(-9.5,16.5) A9(-8.5,16.5) A10(-7.5,16.5) A11(-6.5,16.5) A12(-5.5,16.5) A13(-4.5,16.5) A14(-3.5,16.5) A15(-2.5,16.5) A16(-1.5,16.5) A17(-0.5,16.5) A18(0.5,16.5) A19(1.5,16.5) A20(2.5,16.5) A21(3.5,16.5) A22(4.5,16.5) A23(5.5,16.5) A24(6.5,16.5) A25(7.5,16.5) A26(8.5,16.5) A27(9.5,16.5) A28(10.5,16.5) A29(11.5,16.5) A30(12.5,16.5) A31(13.5,16.5) A32(14.5,16.5) A33(15.5,16.5) AA1(-16.5,-3.5) AA2(-15.5,-3.5) AA3(-14.5,-3.5) AA4(-13.5,-3.5) AA5(-12.5,-3.5) AA6(-11.5,-3.5) AA7(-10.5,-3.5) AA8(-9.5,-3.5) AA9(-8.5,-3.5) AA10(-7.5,-3.5) AA11(-6.5,-3.5) AA12(-5.5,-3.5) AA13(-4.5,-3.5) AA14(-3.5,-3.5) AA15(-2.5,-3.5) AA16(-1.5,-3.5) AA17(-0.5,-3.5) AA18(0.5,-3.5) AA19(1.5,-3.5) AA20(2.5,-3.5) AA21(3.5,-3.5) AA22(4.5,-3.5) AA23(5.5,-3.5) AA24(6.5,-3.5) AA25(7.5,-3.5) AA26(8.5,-3.5) AA27(9.5,-3.5) AA28(10.5,-3.5) AA29(11.5,-3.5) AA30(12.5,-3.5) AA31(13.5,-3.5) AA32(14.5,-3.5) AA33(15.5,-3.5) AA34(16.5,-3.5) AB1(-16.5,-4.5) AB2(-15.5,-4.5) AB3(-14.5,-4.5) AB4(-13.5,-4.5) AB5(-12.5,-4.5) AB6(-11.5,-4.5) AB7(-10.5,-4.5) AB8(-9.5,-4.5) AB9(-8.5,-4.5) AB10(-7.5,-4.5) AB11(-6.5,-4.5) AB12(-5.5,-4.5) AB13(-4.5,-4.5) AB14(-3.5,-4.5) AB15(-2.5,-4.5) AB16(-1.5,-4.5) AB17(-0.5,-4.5) AB18(0.5,-4.5) AB19(1.5,-4.5) AB20(2.5,-4.5) AB21(3.5,-4.5) AB22(4.5,-4.5) AB23(5.5,-4.5) AB24(6.5,-4.5) AB25(7.5,-4.5) AB26(8.5,-4.5) AB27(9.5,-4.5) AB28(10.5,-4.5) AB29(11.5,-4.5) AB30(12.5,-4.5) AB31(13.5,-4.5) AB32(14.5,-4.5) AB33(15.5,-4.5) AB34(16.5,-4.5) AC1(-16.5,-5.5) AC2(-15.5,-5.5) AC3(-14.5,-5.5) AC4(-13.5,-5.5) AC5(-12.5,-5.5) AC6(-11.5,-5.5) AC7(-10.5,-5.5) AC8(-9.5,-5.5) AC9(-8.5,-5.5) AC10(-7.5,-5.5) AC11(-6.5,-5.5) AC12(-5.5,-5.5) AC13(-4.5,-5.5) AC14(-3.5,-5.5) AC15(-2.5,-5.5) AC16(-1.5,-5.5) AC17(-0.5,-5.5) AC18(0.5,-5.5) AC19(1.5,-5.5) AC20(2.5,-5.5) AC21(3.5,-5.5) AC22(4.5,-5.5) AC23(5.5,-5.5) AC24(6.5,-5.5) AC25(7.5,-5.5) AC26(8.5,-5.5) AC27(9.5,-5.5) AC28(10.5,-5.5) AC29(11.5,-5.5) AC30(12.5,-5.5) AC31(13.5,-5.5) AC32(14.5,-5.5) AC33(15.5,-5.5) AC34(16.5,-5.5) AD1(-16.5,-6.5) AD2(-15.5,-6.5) AD3(-14.5,-6.5) AD4(-13.5,-6.5) AD5(-12.5,-6.5) AD6(-11.5,-6.5) AD7(-10.5,-6.5) AD8(-9.5,-6.5) AD9(-8.5,-6.5) AD10(-7.5,-6.5) AD11(-6.5,-6.5) AD12(-5.5,-6.5) AD13(-4.5,-6.5) AD14(-3.5,-6.5) AD15(-2.5,-6.5) AD16(-1.5,-6.5) AD17(-0.5,-6.5) AD18(0.5,-6.5) AD19(1.5,-6.5) AD20(2.5,-6.5) AD21(3.5,-6.5) AD22(4.5,-6.5) AD23(5.5,-6.5) AD24(6.5,-6.5) AD25(7.5,-6.5) AD26(8.5,-6.5) AD27(9.5,-6.5) AD28(10.5,-6.5) AD29(11.5,-6.5) AD30(12.5,-6.5) AD31(13.5,-6.5) AD32(14.5,-6.5) AD33(15.5,-6.5) AD34(16.5,-6.5) AE1(-16.5,-7.5) AE2(-15.5,-7.5) AE3(-14.5,-7.5) AE4(-13.5,-7.5) AE5(-12.5,-7.5) AE6(-11.5,-7.5) AE7(-10.5,-7.5) AE8(-9.5,-7.5) AE9(-8.5,-7.5) AE10(-7.5,-7.5) AE11(-6.5,-7.5) AE12(-5.5,-7.5) AE13(-4.5,-7.5) AE14(-3.5,-7.5) AE15(-2.5,-7.5) AE16(-1.5,-7.5) AE17(-0.5,-7.5) AE18(0.5,-7.5) AE19(1.5,-7.5) AE20(2.5,-7.5) AE21(3.5,-7.5) AE22(4.5,-7.5) AE23(5.5,-7.5) AE24(6.5,-7.5) AE25(7.5,-7.5) AE26(8.5,-7.5) AE27(9.5,-7.5) AE28(10.5,-7.5) AE29(11.5,-7.5) AE30(12.5,-7.5) AE31(13.5,-7.5) AE32(14.5,-7.5) AE33(15.5,-7.5) AE34(16.5,-7.5) AF1(-16.5,-8.5) AF2(-15.5,-8.5) AF3(-14.5,-8.5) AF4(-13.5,-8.5) AF5(-12.5,-8.5) AF6(-11.5,-8.5) AF7(-10.5,-8.5) AF8(-9.5,-8.5) AF9(-8.5,-8.5) AF10(-7.5,-8.5) AF11(-6.5,-8.5) AF12(-5.5,-8.5) AF13(-4.5,-8.5) AF14(-3.5,-8.5) AF15(-2.5,-8.5) AF16(-1.5,-8.5) AF17(-0.5,-8.5) AF18(0.5,-8.5) AF19(1.5,-8.5) AF20(2.5,-8.5) AF21(3.5,-8.5) AF22(4.5,-8.5) AF23(5.5,-8.5) AF24(6.5,-8.5) AF25(7.5,-8.5) AF26(8.5,-8.5) AF27(9.5,-8.5) AF28(10.5,-8.5) AF29(11.5,-8.5) AF30(12.5,-8.5) AF31(13.5,-8.5) AF32(14.5,-8.5) AF33(15.5,-8.5) AF34(16.5,-8.5) AG1(-16.5,-9.5) AG2(-15.5,-9.5) AG3(-14.5,-9.5) AG4(-13.5,-9.5) AG5(-12.5,-9.5) AG6(-11.5,-9.5) AG7(-10.5,-9.5) AG8(-9.5,-9.5) AG9(-8.5,-9.5) AG10(-7.5,-9.5) AG11(-6.5,-9.5) AG12(-5.5,-9.5) AG13(-4.5,-9.5) AG14(-3.5,-9.5) AG15(-2.5,-9.5) AG16(-1.5,-9.5) AG17(-0.5,-9.5) AG18(0.5,-9.5) AG19(1.5,-9.5) AG20(2.5,-9.5) AG21(3.5,-9.5) AG22(4.5,-9.5) AG23(5.5,-9.5) AG24(6.5,-9.5) AG25(7.5,-9.5) AG26(8.5,-9.5) AG27(9.5,-9.5) AG28(10.5,-9.5) AG29(11.5,-9.5) AG30(12.5,-9.5) AG31(13.5,-9.5) AG32(14.5,-9.5) AG33(15.5,-9.5) AG34(16.5,-9.5) AH1(-16.5,-10.5) AH2(-15.5,-10.5) AH3(-14.5,-10.5) AH4(-13.5,-10.5) AH5(-12.5,-10.5) AH6(-11.5,-10.5) AH7(-10.5,-10.5) AH8(-9.5,-10.5) AH9(-8.5,-10.5) AH10(-7.5,-10.5) AH11(-6.5,-10.5) AH12(-5.5,-10.5) AH13(-4.5,-10.5) AH14(-3.5,-10.5) AH15(-2.5,-10.5) AH16(-1.5,-10.5) AH17(-0.5,-10.5) AH18(0.5,-10.5) AH19(1.5,-10.5) AH20(2.5,-10.5) AH21(3.5,-10.5) AH22(4.5,-10.5) AH23(5.5,-10.5) AH24(6.5,-10.5) AH25(7.5,-10.5) AH26(8.5,-10.5) AH27(9.5,-10.5) AH28(10.5,-10.5) AH29(11.5,-10.5) AH30(12.5,-10.5) AH31(13.5,-10.5) AH32(14.5,-10.5) AH33(15.5,-10.5) AH34(16.5,-10.5) AJ1(-16.5,-11.5) AJ2(-15.5,-11.5) AJ3(-14.5,-11.5) AJ4(-13.5,-11.5) AJ5(-12.5,-11.5) AJ6(-11.5,-11.5) AJ7(-10.5,-11.5) AJ8(-9.5,-11.5) AJ9(-8.5,-11.5) AJ10(-7.5,-11.5) AJ11(-6.5,-11.5) AJ12(-5.5,-11.5) AJ13(-4.5,-11.5) AJ14(-3.5,-11.5) AJ15(-2.5,-11.5) AJ16(-1.5,-11.5) AJ17(-0.5,-11.5) AJ18(0.5,-11.5) AJ19(1.5,-11.5) AJ20(2.5,-11.5) AJ21(3.5,-11.5) AJ22(4.5,-11.5) AJ23(5.5,-11.5) AJ24(6.5,-11.5) AJ25(7.5,-11.5) AJ26(8.5,-11.5) AJ27(9.5,-11.5) AJ28(10.5,-11.5) AJ29(11.5,-11.5) AJ30(12.5,-11.5) AJ31(13.5,-11.5) AJ32(14.5,-11.5) AJ33(15.5,-11.5) AJ34(16.5,-11.5) AK1(-16.5,-12.5) AK2(-15.5,-12.5) AK3(-14.5,-12.5) AK4(-13.5,-12.5) AK5(-12.5,-12.5) AK6(-11.5,-12.5) AK7(-10.5,-12.5) AK8(-9.5,-12.5) AK9(-8.5,-12.5) AK10(-7.5,-12.5) AK11(-6.5,-12.5) AK12(-5.5,-12.5) AK13(-4.5,-12.5) AK14(-3.5,-12.5) AK15(-2.5,-12.5) AK16(-1.5,-12.5) AK17(-0.5,-12.5) AK18(0.5,-12.5) AK19(1.5,-12.5) AK20(2.5,-12.5) AK21(3.5,-12.5) AK22(4.5,-12.5) AK23(5.5,-12.5) AK24(6.5,-12.5) AK25(7.5,-12.5) AK26(8.5,-12.5) AK27(9.5,-12.5) AK28(10.5,-12.5) AK29(11.5,-12.5) AK30(12.5,-12.5) AK31(13.5,-12.5) AK32(14.5,-12.5) AK33(15.5,-12.5) AK34(16.5,-12.5) AL1(-16.5,-13.5) AL2(-15.5,-13.5) AL3(-14.5,-13.5) AL4(-13.5,-13.5) AL5(-12.5,-13.5) AL6(-11.5,-13.5) AL7(-10.5,-13.5) AL8(-9.5,-13.5) AL9(-8.5,-13.5) AL10(-7.5,-13.5) AL11(-6.5,-13.5) AL12(-5.5,-13.5) AL13(-4.5,-13.5) AL14(-3.5,-13.5) AL15(-2.5,-13.5) AL16(-1.5,-13.5) AL17(-0.5,-13.5) AL18(0.5,-13.5) AL19(1.5,-13.5) AL20(2.5,-13.5) AL21(3.5,-13.5) AL22(4.5,-13.5) AL23(5.5,-13.5) AL24(6.5,-13.5) AL25(7.5,-13.5) AL26(8.5,-13.5) AL27(9.5,-13.5) AL28(10.5,-13.5) AL29(11.5,-13.5) AL30(12.5,-13.5) AL31(13.5,-13.5) AL32(14.5,-13.5) AL33(15.5,-13.5) AL34(16.5,-13.5) AM1(-16.5,-14.5) AM2(-15.5,-14.5) AM3(-14.5,-14.5) AM4(-13.5,-14.5) AM5(-12.5,-14.5) AM6(-11.5,-14.5) AM7(-10.5,-14.5) AM8(-9.5,-14.5) AM9(-8.5,-14.5) AM10(-7.5,-14.5) AM11(-6.5,-14.5) AM12(-5.5,-14.5) AM13(-4.5,-14.5) AM14(-3.5,-14.5) AM15(-2.5,-14.5) AM16(-1.5,-14.5) AM17(-0.5,-14.5) AM18(0.5,-14.5) AM19(1.5,-14.5) AM20(2.5,-14.5) AM21(3.5,-14.5) AM22(4.5,-14.5) AM23(5.5,-14.5) AM24(6.5,-14.5) AM25(7.5,-14.5) AM26(8.5,-14.5) AM27(9.5,-14.5) AM28(10.5,-14.5) AM29(11.5,-14.5) AM30(12.5,-14.5) AM31(13.5,-14.5) AM32(14.5,-14.5) AM33(15.5,-14.5) AM34(16.5,-14.5) AN1(-16.5,-15.5) AN2(-15.5,-15.5) AN3(-14.5,-15.5) AN4(-13.5,-15.5) AN5(-12.5,-15.5) AN6(-11.5,-15.5) AN7(-10.5,-15.5) AN8(-9.5,-15.5) AN9(-8.5,-15.5) AN10(-7.5,-15.5) AN11(-6.5,-15.5) AN12(-5.5,-15.5) AN13(-4.5,-15.5) AN14(-3.5,-15.5) AN15(-2.5,-15.5) AN16(-1.5,-15.5) AN17(-0.5,-15.5) AN18(0.5,-15.5) AN19(1.5,-15.5) AN20(2.5,-15.5) AN21(3.5,-15.5) AN22(4.5,-15.5) AN23(5.5,-15.5) AN24(6.5,-15.5) AN25(7.5,-15.5) AN26(8.5,-15.5) AN27(9.5,-15.5) AN28(10.5,-15.5) AN29(11.5,-15.5) AN30(12.5,-15.5) AN31(13.5,-15.5) AN32(14.5,-15.5) AN33(15.5,-15.5) AN34(16.5,-15.5) AP2(-15.5,-16.5) AP3(-14.5,-16.5) AP4(-13.5,-16.5) AP5(-12.5,-16.5) AP6(-11.5,-16.5) AP7(-10.5,-16.5) AP8(-9.5,-16.5) AP9(-8.5,-16.5) AP10(-7.5,-16.5) AP11(-6.5,-16.5) AP12(-5.5,-16.5) AP13(-4.5,-16.5) AP14(-3.5,-16.5) AP15(-2.5,-16.5) AP16(-1.5,-16.5) AP17(-0.5,-16.5) AP18(0.5,-16.5) AP19(1.5,-16.5) AP20(2.5,-16.5) AP21(3.5,-16.5) AP22(4.5,-16.5) AP23(5.5,-16.5) AP24(6.5,-16.5) AP25(7.5,-16.5) AP26(8.5,-16.5) AP27(9.5,-16.5) AP28(10.5,-16.5) AP29(11.5,-16.5) AP30(12.5,-16.5) AP31(13.5,-16.5) AP32(14.5,-16.5) AP33(15.5,-16.5) B1(-16.5,15.5) B2(-15.5,15.5) B3(-14.5,15.5) B4(-13.5,15.5) B5(-12.5,15.5) B6(-11.5,15.5) B7(-10.5,15.5) B8(-9.5,15.5) B9(-8.5,15.5) B10(-7.5,15.5) B11(-6.5,15.5) B12(-5.5,15.5) B13(-4.5,15.5) B14(-3.5,15.5) B15(-2.5,15.5) B16(-1.5,15.5) B17(-0.5,15.5) B18(0.5,15.5) B19(1.5,15.5) B20(2.5,15.5) B21(3.5,15.5) B22(4.5,15.5) B23(5.5,15.5) B24(6.5,15.5) B25(7.5,15.5) B26(8.5,15.5) B27(9.5,15.5) B28(10.5,15.5) B29(11.5,15.5) B30(12.5,15.5) B31(13.5,15.5) B32(14.5,15.5) B33(15.5,15.5) B34(16.5,15.5) C1(-16.5,14.5) C2(-15.5,14.5) C3(-14.5,14.5) C4(-13.5,14.5) C5(-12.5,14.5) C6(-11.5,14.5) C7(-10.5,14.5) C8(-9.5,14.5) C9(-8.5,14.5) C10(-7.5,14.5) C11(-6.5,14.5) C12(-5.5,14.5) C13(-4.5,14.5) C14(-3.5,14.5) C15(-2.5,14.5) C16(-1.5,14.5) C17(-0.5,14.5) C18(0.5,14.5) C19(1.5,14.5) C20(2.5,14.5) C21(3.5,14.5) C22(4.5,14.5) C23(5.5,14.5) C24(6.5,14.5) C25(7.5,14.5) C26(8.5,14.5) C27(9.5,14.5) C28(10.5,14.5) C29(11.5,14.5) C30(12.5,14.5) C31(13.5,14.5) C32(14.5,14.5) C33(15.5,14.5) C34(16.5,14.5) D1(-16.5,13.5) D2(-15.5,13.5) D3(-14.5,13.5) D4(-13.5,13.5) D5(-12.5,13.5) D6(-11.5,13.5) D7(-10.5,13.5) D8(-9.5,13.5) D9(-8.5,13.5) D10(-7.5,13.5) D11(-6.5,13.5) D12(-5.5,13.5) D13(-4.5,13.5) D14(-3.5,13.5) D15(-2.5,13.5) D16(-1.5,13.5) D17(-0.5,13.5) D18(0.5,13.5) D19(1.5,13.5) D20(2.5,13.5) D21(3.5,13.5) D22(4.5,13.5) D23(5.5,13.5) D24(6.5,13.5) D25(7.5,13.5) D26(8.5,13.5) D27(9.5,13.5) D28(10.5,13.5) D29(11.5,13.5) D30(12.5,13.5) D31(13.5,13.5) D32(14.5,13.5) D33(15.5,13.5) D34(16.5,13.5) E1(-16.5,12.5) E2(-15.5,12.5) E3(-14.5,12.5) E4(-13.5,12.5) E5(-12.5,12.5) E6(-11.5,12.5) E7(-10.5,12.5) E8(-9.5,12.5) E9(-8.5,12.5) E10(-7.5,12.5) E11(-6.5,12.5) E12(-5.5,12.5) E13(-4.5,12.5) E14(-3.5,12.5) E15(-2.5,12.5) E16(-1.5,12.5) E17(-0.5,12.5) E18(0.5,12.5) E19(1.5,12.5) E20(2.5,12.5) E21(3.5,12.5) E22(4.5,12.5) E23(5.5,12.5) E24(6.5,12.5) E25(7.5,12.5) E26(8.5,12.5) E27(9.5,12.5) E28(10.5,12.5) E29(11.5,12.5) E30(12.5,12.5) E31(13.5,12.5) E32(14.5,12.5) E33(15.5,12.5) E34(16.5,12.5) F1(-16.5,11.5) F2(-15.5,11.5) F3(-14.5,11.5) F4(-13.5,11.5) F5(-12.5,11.5) F6(-11.5,11.5) F7(-10.5,11.5) F8(-9.5,11.5) F9(-8.5,11.5) F10(-7.5,11.5) F11(-6.5,11.5) F12(-5.5,11.5) F13(-4.5,11.5) F14(-3.5,11.5) F15(-2.5,11.5) F16(-1.5,11.5) F17(-0.5,11.5) F18(0.5,11.5) F19(1.5,11.5) F20(2.5,11.5) F21(3.5,11.5) F22(4.5,11.5) F23(5.5,11.5) F24(6.5,11.5) F25(7.5,11.5) F26(8.5,11.5) F27(9.5,11.5) F28(10.5,11.5) F29(11.5,11.5) F30(12.5,11.5) F31(13.5,11.5) F32(14.5,11.5) F33(15.5,11.5) F34(16.5,11.5) G1(-16.5,10.5) G2(-15.5,10.5) G3(-14.5,10.5) G4(-13.5,10.5) G5(-12.5,10.5) G6(-11.5,10.5) G7(-10.5,10.5) G8(-9.5,10.5) G9(-8.5,10.5) G10(-7.5,10.5) G11(-6.5,10.5) G12(-5.5,10.5) G13(-4.5,10.5) G14(-3.5,10.5) G15(-2.5,10.5) G16(-1.5,10.5) G17(-0.5,10.5) G18(0.5,10.5) G19(1.5,10.5) G20(2.5,10.5) G21(3.5,10.5) G22(4.5,10.5) G23(5.5,10.5) G24(6.5,10.5) G25(7.5,10.5) G26(8.5,10.5) G27(9.5,10.5) G28(10.5,10.5) G29(11.5,10.5) G30(12.5,10.5) G31(13.5,10.5) G32(14.5,10.5) G33(15.5,10.5) G34(16.5,10.5) H1(-16.5,9.5) H2(-15.5,9.5) H3(-14.5,9.5) H4(-13.5,9.5) H5(-12.5,9.5) H6(-11.5,9.5) H7(-10.5,9.5) H8(-9.5,9.5) H9(-8.5,9.5) H10(-7.5,9.5) H11(-6.5,9.5) H12(-5.5,9.5) H13(-4.5,9.5) H14(-3.5,9.5) H15(-2.5,9.5) H16(-1.5,9.5) H17(-0.5,9.5) H18(0.5,9.5) H19(1.5,9.5) H20(2.5,9.5) H21(3.5,9.5) H22(4.5,9.5) H23(5.5,9.5) H24(6.5,9.5) H25(7.5,9.5) H26(8.5,9.5) H27(9.5,9.5) H28(10.5,9.5) H29(11.5,9.5) H30(12.5,9.5) H31(13.5,9.5) H32(14.5,9.5) H33(15.5,9.5) H34(16.5,9.5) J1(-16.5,8.5) J2(-15.5,8.5) J3(-14.5,8.5) J4(-13.5,8.5) J5(-12.5,8.5) J6(-11.5,8.5) J7(-10.5,8.5) J8(-9.5,8.5) J9(-8.5,8.5) J10(-7.5,8.5) J11(-6.5,8.5) J12(-5.5,8.5) J13(-4.5,8.5) J14(-3.5,8.5) J15(-2.5,8.5) J16(-1.5,8.5) J17(-0.5,8.5) J18(0.5,8.5) J19(1.5,8.5) J20(2.5,8.5) J21(3.5,8.5) J22(4.5,8.5) J23(5.5,8.5) J24(6.5,8.5) J25(7.5,8.5) J26(8.5,8.5) J27(9.5,8.5) J28(10.5,8.5) J29(11.5,8.5) J30(12.5,8.5) J31(13.5,8.5) J32(14.5,8.5) J33(15.5,8.5) J34(16.5,8.5) K1(-16.5,7.5) K2(-15.5,7.5) K3(-14.5,7.5) K4(-13.5,7.5) K5(-12.5,7.5) K6(-11.5,7.5) K7(-10.5,7.5) K8(-9.5,7.5) K9(-8.5,7.5) K10(-7.5,7.5) K11(-6.5,7.5) K12(-5.5,7.5) K13(-4.5,7.5) K14(-3.5,7.5) K15(-2.5,7.5) K16(-1.5,7.5) K17(-0.5,7.5) K18(0.5,7.5) K19(1.5,7.5) K20(2.5,7.5) K21(3.5,7.5) K22(4.5,7.5) K23(5.5,7.5) K24(6.5,7.5) K25(7.5,7.5) K26(8.5,7.5) K27(9.5,7.5) K28(10.5,7.5) K29(11.5,7.5) K30(12.5,7.5) K31(13.5,7.5) K32(14.5,7.5) K33(15.5,7.5) K34(16.5,7.5) L1(-16.5,6.5) L2(-15.5,6.5) L3(-14.5,6.5) L4(-13.5,6.5) L5(-12.5,6.5) L6(-11.5,6.5) L7(-10.5,6.5) L8(-9.5,6.5) L9(-8.5,6.5) L10(-7.5,6.5) L11(-6.5,6.5) L12(-5.5,6.5) L13(-4.5,6.5) L14(-3.5,6.5) L15(-2.5,6.5) L16(-1.5,6.5) L17(-0.5,6.5) L18(0.5,6.5) L19(1.5,6.5) L20(2.5,6.5) L21(3.5,6.5) L22(4.5,6.5) L23(5.5,6.5) L24(6.5,6.5) L25(7.5,6.5) L26(8.5,6.5) L27(9.5,6.5) L28(10.5,6.5) L29(11.5,6.5) L30(12.5,6.5) L31(13.5,6.5) L32(14.5,6.5) L33(15.5,6.5) L34(16.5,6.5) M1(-16.5,5.5) M2(-15.5,5.5) M3(-14.5,5.5) M4(-13.5,5.5) M5(-12.5,5.5) M6(-11.5,5.5) M7(-10.5,5.5) M8(-9.5,5.5) M9(-8.5,5.5) M10(-7.5,5.5) M11(-6.5,5.5) M12(-5.5,5.5) M13(-4.5,5.5) M14(-3.5,5.5) M15(-2.5,5.5) M16(-1.5,5.5) M17(-0.5,5.5) M18(0.5,5.5) M19(1.5,5.5) M20(2.5,5.5) M21(3.5,5.5) M22(4.5,5.5) M23(5.5,5.5) M24(6.5,5.5) M25(7.5,5.5) M26(8.5,5.5) M27(9.5,5.5) M28(10.5,5.5) M29(11.5,5.5) M30(12.5,5.5) M31(13.5,5.5) M32(14.5,5.5) M33(15.5,5.5) M34(16.5,5.5) N1(-16.5,4.5) N2(-15.5,4.5) N3(-14.5,4.5) N4(-13.5,4.5) N5(-12.5,4.5) N6(-11.5,4.5) N7(-10.5,4.5) N8(-9.5,4.5) N9(-8.5,4.5) N10(-7.5,4.5) N11(-6.5,4.5) N12(-5.5,4.5) N13(-4.5,4.5) N14(-3.5,4.5) N15(-2.5,4.5) N16(-1.5,4.5) N17(-0.5,4.5) N18(0.5,4.5) N19(1.5,4.5) N20(2.5,4.5) N21(3.5,4.5) N22(4.5,4.5) N23(5.5,4.5) N24(6.5,4.5) N25(7.5,4.5) N26(8.5,4.5) N27(9.5,4.5) N28(10.5,4.5) N29(11.5,4.5) N30(12.5,4.5) N31(13.5,4.5) N32(14.5,4.5) N33(15.5,4.5) N34(16.5,4.5) P1(-16.5,3.5) P2(-15.5,3.5) P3(-14.5,3.5) P4(-13.5,3.5) P5(-12.5,3.5) P6(-11.5,3.5) P7(-10.5,3.5) P8(-9.5,3.5) P9(-8.5,3.5) P10(-7.5,3.5) P11(-6.5,3.5) P12(-5.5,3.5) P13(-4.5,3.5) P14(-3.5,3.5) P15(-2.5,3.5) P16(-1.5,3.5) P17(-0.5,3.5) P18(0.5,3.5) P19(1.5,3.5) P20(2.5,3.5) P21(3.5,3.5) P22(4.5,3.5) P23(5.5,3.5) P24(6.5,3.5) P25(7.5,3.5) P26(8.5,3.5) P27(9.5,3.5) P28(10.5,3.5) P29(11.5,3.5) P30(12.5,3.5) P31(13.5,3.5) P32(14.5,3.5) P33(15.5,3.5) P34(16.5,3.5) R1(-16.5,2.5) R2(-15.5,2.5) R3(-14.5,2.5) R4(-13.5,2.5) R5(-12.5,2.5) R6(-11.5,2.5) R7(-10.5,2.5) R8(-9.5,2.5) R9(-8.5,2.5) R10(-7.5,2.5) R11(-6.5,2.5) R12(-5.5,2.5) R13(-4.5,2.5) R14(-3.5,2.5) R15(-2.5,2.5) R16(-1.5,2.5) R17(-0.5,2.5) R18(0.5,2.5) R19(1.5,2.5) R20(2.5,2.5) R21(3.5,2.5) R22(4.5,2.5) R23(5.5,2.5) R24(6.5,2.5) R25(7.5,2.5) R26(8.5,2.5) R27(9.5,2.5) R28(10.5,2.5) R29(11.5,2.5) R30(12.5,2.5) R31(13.5,2.5) R32(14.5,2.5) R33(15.5,2.5) R34(16.5,2.5) T1(-16.5,1.5) T2(-15.5,1.5) T3(-14.5,1.5) T4(-13.5,1.5) T5(-12.5,1.5) T6(-11.5,1.5) T7(-10.5,1.5) T8(-9.5,1.5) T9(-8.5,1.5) T10(-7.5,1.5) T11(-6.5,1.5) T12(-5.5,1.5) T13(-4.5,1.5) T14(-3.5,1.5) T15(-2.5,1.5) T16(-1.5,1.5) T17(-0.5,1.5) T18(0.5,1.5) T19(1.5,1.5) T20(2.5,1.5) T21(3.5,1.5) T22(4.5,1.5) T23(5.5,1.5) T24(6.5,1.5) T25(7.5,1.5) T26(8.5,1.5) T27(9.5,1.5) T28(10.5,1.5) T29(11.5,1.5) T30(12.5,1.5) T31(13.5,1.5) T32(14.5,1.5) T33(15.5,1.5) T34(16.5,1.5) U1(-16.5,0.5) U2(-15.5,0.5) U3(-14.5,0.5) U4(-13.5,0.5) U5(-12.5,0.5) U6(-11.5,0.5) U7(-10.5,0.5) U8(-9.5,0.5) U9(-8.5,0.5) U10(-7.5,0.5) U11(-6.5,0.5) U12(-5.5,0.5) U13(-4.5,0.5) U14(-3.5,0.5) U15(-2.5,0.5) U16(-1.5,0.5) U17(-0.5,0.5) U18(0.5,0.5) U19(1.5,0.5) U20(2.5,0.5) U21(3.5,0.5) U22(4.5,0.5) U23(5.5,0.5) U24(6.5,0.5) U25(7.5,0.5) U26(8.5,0.5) U27(9.5,0.5) U28(10.5,0.5) U29(11.5,0.5) U30(12.5,0.5) U31(13.5,0.5) U32(14.5,0.5) U33(15.5,0.5) U34(16.5,0.5) V1(-16.5,-0.5) V2(-15.5,-0.5) V3(-14.5,-0.5) V4(-13.5,-0.5) V5(-12.5,-0.5) V6(-11.5,-0.5) V7(-10.5,-0.5) V8(-9.5,-0.5) V9(-8.5,-0.5) V10(-7.5,-0.5) V11(-6.5,-0.5) V12(-5.5,-0.5) V13(-4.5,-0.5) V14(-3.5,-0.5) V15(-2.5,-0.5) V16(-1.5,-0.5) V17(-0.5,-0.5) V18(0.5,-0.5) V19(1.5,-0.5) V20(2.5,-0.5) V21(3.5,-0.5) V22(4.5,-0.5) V23(5.5,-0.5) V24(6.5,-0.5) V25(7.5,-0.5) V26(8.5,-0.5) V27(9.5,-0.5) V28(10.5,-0.5) V29(11.5,-0.5) V30(12.5,-0.5) V31(13.5,-0.5) V32(14.5,-0.5) V33(15.5,-0.5) V34(16.5,-0.5) W1(-16.5,-1.5) W2(-15.5,-1.5) W3(-14.5,-1.5) W4(-13.5,-1.5) W5(-12.5,-1.5) W6(-11.5,-1.5) W7(-10.5,-1.5) W8(-9.5,-1.5) W9(-8.5,-1.5) W10(-7.5,-1.5) W11(-6.5,-1.5) W12(-5.5,-1.5) W13(-4.5,-1.5) W14(-3.5,-1.5) W15(-2.5,-1.5) W16(-1.5,-1.5) W17(-0.5,-1.5) W18(0.5,-1.5) W19(1.5,-1.5) W20(2.5,-1.5) W21(3.5,-1.5) W22(4.5,-1.5) W23(5.5,-1.5) W24(6.5,-1.5) W25(7.5,-1.5) W26(8.5,-1.5) W27(9.5,-1.5) W28(10.5,-1.5) W29(11.5,-1.5) W30(12.5,-1.5) W31(13.5,-1.5) W32(14.5,-1.5) W33(15.5,-1.5) W34(16.5,-1.5) Y1(-16.5,-2.5) Y2(-15.5,-2.5) Y3(-14.5,-2.5) Y4(-13.5,-2.5) Y5(-12.5,-2.5) Y6(-11.5,-2.5) Y7(-10.5,-2.5) Y8(-9.5,-2.5) Y9(-8.5,-2.5) Y10(-7.5,-2.5) Y11(-6.5,-2.5) Y12(-5.5,-2.5) Y13(-4.5,-2.5) Y14(-3.5,-2.5) Y15(-2.5,-2.5) Y16(-1.5,-2.5) Y17(-0.5,-2.5) Y18(0.5,-2.5) Y19(1.5,-2.5) Y20(2.5,-2.5) Y21(3.5,-2.5) Y22(4.5,-2.5) Y23(5.5,-2.5) Y24(6.5,-2.5) Y25(7.5,-2.5) Y26(8.5,-2.5) Y27(9.5,-2.5) Y28(10.5,-2.5) Y29(11.5,-2.5) Y30(12.5,-2.5) Y31(13.5,-2.5) Y32(14.5,-2.5) Y33(15.5,-2.5) Y34(16.5,-2.5)
Top Overlay:
  circle w0.25: c-18.15,16.5 r0.125
  region: -16.5,17.5 -17.5,16.5 -17.5,17.5
  lines w0.2: -17.5,16.5 -16.5,17.5 ; -17.5,-17.5 -17.5,17.5 17.5,17.5 17.5,-17.5 -17.5,-17.5
Mechanical 13:
  lines w0.1: -17.5,-17.5 -17.5,17.5 17.5,17.5 17.5,-17.5 -17.5,-17.5
Mechanical 15:
  lines w0.1: -0.5,0 0.5,0 ; 0,-0.5 0,0.5 ; -18.5,-18.5 -18.5,18.5 18.5,18.5 18.5,-18.5 -18.5,-18.5
3D body: height 3.4, standoff 0, extent -17.5,-17.5 17.5,17.5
